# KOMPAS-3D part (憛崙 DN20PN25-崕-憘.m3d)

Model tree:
1. Объединить компоненты:1
2. Эскиз:1
3. Операция выдавливания:1
     Расстояние 1 = 14
4. Фаска:1
     Угол = 45; Длина 1 = 2; Длина 2 = 2

Referenced files in D:\Савин\!СЕНСОР\3D для заказчика\СЕНС\СЕНС DN15PN25-НО\Сборка\: Клапан DN20.a3d
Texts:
  СЕНС DN20PN25-НО-СВ
  ООО НПП Сенсор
